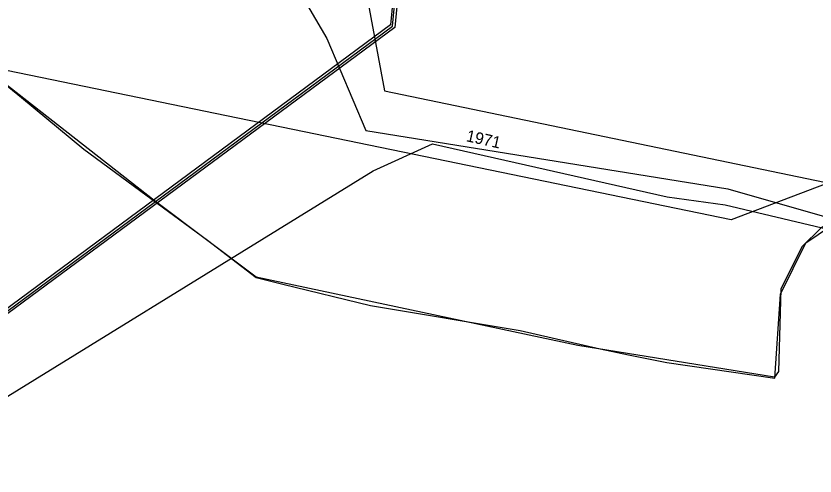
# Model space of a CAD drawing. Extents: x -599951 to -598963, y -1164095 to -1162939.
# Drawn here: x -599878 to -599823.1, y -1163091.3 to -1163059.7 of the extents above; entities that cross this region are included whole.
import ezdxf

# ---------------------------------------------------------------- set-up
doc = ezdxf.new("R2010")
doc.units = 0
for name, color, linetype in [('Vrstva 12', 7, 'Continuous'), ('Vrstva 13', 7, 'Continuous'), ('Vrstva 15', 7, 'Continuous'), ('Vrstva 25', 7, 'Continuous'), ('Vrstva 42', 7, 'Continuous')]:
    doc.layers.add(name, color=color, linetype=linetype)

msp = doc.modelspace()

# ---------------------------------------------------------------- linework, layer by layer
at = {"layer": 'Vrstva 12'}
for points in [[(-599860.12, -1163055.28), (-599854.02, -1163057.48), (-599852.65, -1163064.87), (-599821.22, -1163071.4), (-599813.284, -1163073.958)], [(-599860.12, -1163055.28), (-599856.6, -1163061.29), (-599853.92, -1163067.61), (-599829.07, -1163071.62), (-599820.67, -1163074.02), (-599813.582, -1163075.481)], [(-599881.93, -1163061.81), (-599877.57, -1163065.33), (-599873.3, -1163068.88), (-599869.04, -1163072.02), (-599864.81, -1163075.13), (-599861.46, -1163077.7), (-599859.62, -1163078.15), (-599853.6, -1163079.62), (-599843.33, -1163081.35), (-599837.84, -1163082.59), (-599835.88, -1163083.02), (-599833.25, -1163083.54), (-599825.85, -1163084.61), (-599825.45, -1163078.85), (-599823.71, -1163075.32), (-599821.18, -1163073.61), (-599813.83, -1163073.27), (-599810.3, -1163071.58), (-599806.61, -1163071.81), (-599801.7, -1163073.46), (-599799.74, -1163072.97)], [(-599884.34, -1163089.42), (-599853.43, -1163070.38), (-599849.34, -1163068.52), (-599833.24, -1163072.17), (-599829.25, -1163072.71), (-599820.85, -1163074.7), (-599813.741, -1163076.296)]]:
    msp.add_lwpolyline(points, dxfattribs=at)
at = {"layer": 'Vrstva 13'}
msp.add_lwpolyline([(-599723.934, -1163082.934), (-599810.529, -1163067.581), (-599818.168, -1163069.687), (-599828.834, -1163073.741), (-599893.625, -1163060.405), (-599895.994, -1163062.158), (-599916.74, -1163078.425)], dxfattribs=at)
at = {"layer": 'Vrstva 25'}
msp.add_lwpolyline([(-599808.402, -1163071.699), (-599810.482, -1163071.501), (-599812.788, -1163072.269), (-599813.69, -1163073.77), (-599816.217, -1163072.822), (-599818.397, -1163072.571), (-599820.247, -1163073.143), (-599822.646, -1163074.266), (-599823.985, -1163075.595), (-599825.425, -1163078.507), (-599825.58, -1163084.161), (-599825.873, -1163084.541), (-599839.367, -1163082.371), (-599861.471, -1163077.668), (-599868.376, -1163072.489), (-599879.004, -1163064.179)], dxfattribs=at)
at = {"layer": 'Vrstva 42'}
for points in [[(-599815.518, -1163019.48), (-599820.791, -1163019.23), (-599821.01, -1163019.37), (-599822.87, -1163019.4), (-599823.02, -1163019.991), (-599823.159, -1163020.568), (-599823.271, -1163021.364), (-599827.714, -1163021.51), (-599835.493, -1163022.702), (-599852.557, -1163025.328), (-599854.173, -1163026.768), (-599855.063, -1163030.103), (-599854.618, -1163032.62), (-599851.529, -1163035.218), (-599847.993, -1163036.016), (-599847.84, -1163036.05), (-599848.693, -1163040.788), (-599851.012, -1163052.737), (-599851.441, -1163055.21), (-599851.947, -1163060.521), (-599893.107, -1163090.941)], [(-599815.518, -1163019.48), (-599820.791, -1163019.23), (-599821.01, -1163019.37), (-599822.87, -1163019.4), (-599823.02, -1163019.991), (-599823.159, -1163020.568), (-599823.271, -1163021.364), (-599827.714, -1163021.51), (-599835.493, -1163022.702), (-599852.557, -1163025.328), (-599854.173, -1163026.768), (-599855.063, -1163030.103), (-599854.618, -1163032.62), (-599851.529, -1163035.218), (-599847.993, -1163036.016), (-599847.84, -1163036.05), (-599848.693, -1163040.788), (-599851.012, -1163052.737), (-599851.441, -1163055.21), (-599851.947, -1163060.521), (-599893.107, -1163090.941)], [(-599823.02, -1163019.991), (-599823.159, -1163020.568), (-599823.271, -1163021.364), (-599827.714, -1163021.51), (-599835.493, -1163022.702), (-599852.557, -1163025.328), (-599854.173, -1163026.768), (-599855.063, -1163030.103), (-599854.618, -1163032.62), (-599851.529, -1163035.218), (-599847.993, -1163036.016), (-599847.84, -1163036.05), (-599848.693, -1163040.788), (-599851.012, -1163052.737), (-599851.441, -1163055.21), (-599851.947, -1163060.521), (-599893.107, -1163090.941)], [(-599823.02, -1163019.991), (-599823.159, -1163020.568), (-599823.271, -1163021.364), (-599827.714, -1163021.51), (-599835.493, -1163022.702), (-599852.557, -1163025.328), (-599854.173, -1163026.768), (-599855.063, -1163030.103), (-599854.618, -1163032.62), (-599851.529, -1163035.218), (-599847.993, -1163036.016), (-599847.84, -1163036.05), (-599848.693, -1163040.788), (-599851.012, -1163052.737), (-599851.441, -1163055.21), (-599851.947, -1163060.521), (-599893.107, -1163090.941)], [(-599823.159, -1163020.568), (-599823.271, -1163021.364), (-599827.714, -1163021.51), (-599835.493, -1163022.702), (-599852.557, -1163025.328), (-599854.173, -1163026.768), (-599855.063, -1163030.103), (-599854.618, -1163032.62), (-599851.529, -1163035.218), (-599847.993, -1163036.016), (-599847.84, -1163036.05), (-599848.693, -1163040.788), (-599851.012, -1163052.737), (-599851.441, -1163055.21), (-599851.947, -1163060.521), (-599893.107, -1163090.941), (-599898.107, -1163096.736), (-599905.507, -1163118.786), (-599909.197, -1163130.516), (-599919.149, -1163160.781), (-599923.658, -1163172.169), (-599928.466, -1163188.373), (-599951.125, -1163247.074)], [(-599823.159, -1163020.568), (-599823.271, -1163021.364), (-599827.714, -1163021.51), (-599835.493, -1163022.702), (-599852.557, -1163025.328), (-599854.173, -1163026.768), (-599855.063, -1163030.103), (-599854.618, -1163032.62), (-599851.529, -1163035.218), (-599847.993, -1163036.016), (-599847.84, -1163036.05), (-599848.693, -1163040.788), (-599851.012, -1163052.737), (-599851.441, -1163055.21), (-599851.947, -1163060.521), (-599893.107, -1163090.941), (-599898.107, -1163096.736), (-599905.507, -1163118.786), (-599909.197, -1163130.516), (-599919.149, -1163160.781), (-599923.658, -1163172.169), (-599928.466, -1163188.373), (-599951.125, -1163247.074)], [(-599823.009, -1163021.656), (-599827.686, -1163021.81), (-599835.447, -1163022.998), (-599852.423, -1163025.612), (-599853.907, -1163026.932), (-599854.757, -1163030.117), (-599854.342, -1163032.46), (-599851.391, -1163034.942), (-599848.08, -1163035.69), (-599848.987, -1163040.732), (-599851.308, -1163052.683), (-599851.739, -1163055.17), (-599852.233, -1163060.359), (-599893.313, -1163090.719)], [(-599823.009, -1163021.656), (-599827.686, -1163021.81), (-599835.447, -1163022.998), (-599852.423, -1163025.612), (-599853.907, -1163026.932), (-599854.757, -1163030.117), (-599854.342, -1163032.46), (-599851.391, -1163034.942), (-599848.08, -1163035.69), (-599848.987, -1163040.732), (-599851.308, -1163052.683), (-599851.739, -1163055.17), (-599852.233, -1163060.359), (-599893.313, -1163090.719)], [(-599742.215, -1163055.552), (-599755.449, -1163053.841), (-599771.375, -1163051.364), (-599782.13, -1163047.795), (-599795.02, -1163044.953), (-599808.565, -1163042.372), (-599820.407, -1163040.592), (-599840.692, -1163037.303), (-599847.928, -1163035.723), (-599848.08, -1163035.69), (-599848.987, -1163040.732), (-599851.308, -1163052.683), (-599851.739, -1163055.17), (-599852.233, -1163060.359), (-599893.313, -1163090.719), (-599898.373, -1163096.584), (-599905.793, -1163118.694), (-599909.483, -1163130.424), (-599919.431, -1163160.679), (-599923.942, -1163172.071), (-599928.754, -1163188.287), (-599951.125, -1163246.248)], [(-599742.215, -1163055.552), (-599755.449, -1163053.841), (-599771.375, -1163051.364), (-599782.13, -1163047.795), (-599795.02, -1163044.953), (-599808.565, -1163042.372), (-599820.407, -1163040.592), (-599840.692, -1163037.303), (-599847.928, -1163035.723), (-599848.08, -1163035.69), (-599848.987, -1163040.732), (-599851.308, -1163052.683), (-599851.739, -1163055.17), (-599852.233, -1163060.359), (-599893.313, -1163090.719), (-599898.373, -1163096.584), (-599905.793, -1163118.694), (-599909.483, -1163130.424), (-599919.431, -1163160.679), (-599923.942, -1163172.071), (-599928.754, -1163188.287), (-599951.125, -1163246.248)], [(-599742.265, -1163055.848), (-599755.491, -1163054.139), (-599771.445, -1163051.656), (-599782.21, -1163048.085), (-599795.08, -1163045.247), (-599808.615, -1163042.668), (-599820.453, -1163040.888), (-599840.748, -1163037.597), (-599847.84, -1163036.05), (-599848.693, -1163040.788), (-599851.012, -1163052.737), (-599851.441, -1163055.21), (-599851.947, -1163060.521), (-599893.107, -1163090.941), (-599898.107, -1163096.736), (-599905.507, -1163118.786), (-599909.197, -1163130.516), (-599919.149, -1163160.781), (-599923.658, -1163172.169), (-599928.466, -1163188.373), (-599951.125, -1163247.074)], [(-599742.265, -1163055.848), (-599755.491, -1163054.139), (-599771.445, -1163051.656), (-599782.21, -1163048.085), (-599795.08, -1163045.247), (-599808.615, -1163042.668), (-599820.453, -1163040.888), (-599840.748, -1163037.597), (-599847.84, -1163036.05), (-599848.693, -1163040.788), (-599851.012, -1163052.737), (-599851.441, -1163055.21), (-599851.947, -1163060.521), (-599893.107, -1163090.941), (-599898.107, -1163096.736), (-599905.507, -1163118.786), (-599909.197, -1163130.516), (-599919.149, -1163160.781), (-599923.658, -1163172.169), (-599928.466, -1163188.373), (-599951.125, -1163247.074)], [(-599928.61, -1163188.33), (-599923.8, -1163172.12), (-599919.29, -1163160.73), (-599909.34, -1163130.47), (-599905.65, -1163118.74), (-599898.24, -1163096.66), (-599893.21, -1163090.83), (-599852.09, -1163060.44), (-599851.59, -1163055.19), (-599851.16, -1163052.71), (-599848.84, -1163040.76), (-599847.96, -1163035.87)]]:
    msp.add_lwpolyline(points, dxfattribs=at)

# ---------------------------------------------------------------- texts
at = {"layer": 'Vrstva 15'}
msp.add_text('1971', height=0.8, rotation=347.4989, dxfattribs=at).set_placement((-599847.084, -1163068.333))

doc.saveas('drawing.dxf')
